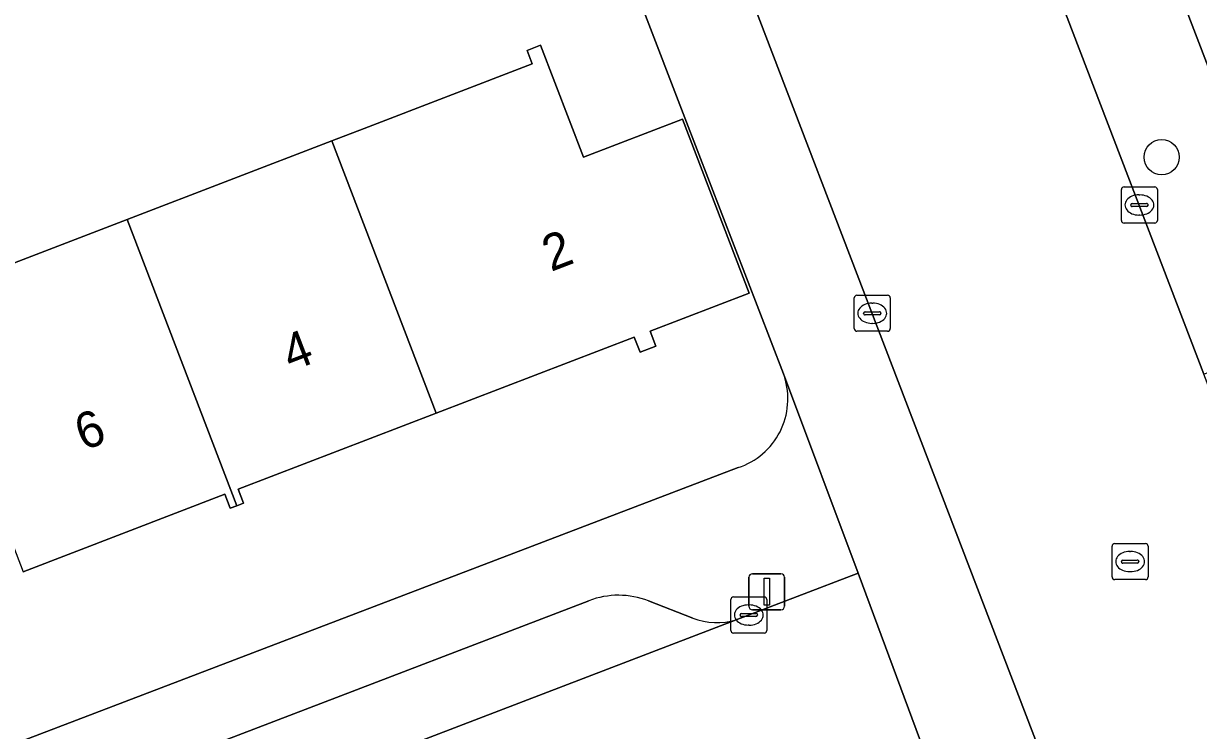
# Model space of a CAD drawing. Extents: x 159262 to 160143, y 383399 to 384319.
# Drawn here: x 159431.92 to 159464.54, y 383799.82 to 383819.43 of the extents above; entities that cross this region are included whole.
import ezdxf

# ---------------------------------------------------------------- set-up
doc = ezdxf.new("R2010")
doc.units = 0
for name, color, linetype in [('IMGEO_Boom', 7, 'Continuous'), ('IMGEO_Erf', 7, 'Continuous'), ('IMGEO_Kolk', 7, 'Continuous'), ('IMGEO_Lichtmast', 7, 'Continuous'), ('IMGEO_Muur', 7, 'Continuous'), ('IMGEO_Pand', 7, 'Continuous'), ('IMGEO_Pand_nummerreeks', 7, 'Continuous'), ('IMGEO_Parkeervlak_open', 7, 'Continuous'), ('IMGEO_Rijbaan_lokaal_gesloten', 7, 'Continuous'), ('IMGEO_Rijbaan_lokaal_open', 7, 'Continuous'), ('IMGEO_Rioolput', 7, 'Continuous'), ('IMGEO_Voetpad_open', 7, 'Continuous')]:
    doc.layers.add(name, color=color, linetype=linetype)

msp = doc.modelspace()

# ---------------------------------------------------------------- linework, layer by layer
at = {"layer": 'IMGEO_Boom'}
msp.add_circle((159463.514, 383815.72), 0.489, dxfattribs=at)
at = {"layer": 'IMGEO_Erf'}
for points in [[(159458.43, 383834.836), (159491.014, 383750), (159493.662, 383742.956), (159500, 383726.102), (159501.344, 383722.528)], [(159450.279, 383816.807), (159446.811, 383825.818), (159443.971, 383824.732), (159437.947, 383822.429), (159437.414, 383823.824), (159433.631, 383822.378), (159432.738, 383824.713), (159417.335, 383818.711), (159417.833, 383817.432), (159414.014, 383815.943), (159410.168, 383814.444), (159409.503, 383816.15), (159382.374, 383805.575), (159383.454, 383802.753), (159384.533, 383799.932), (159385.613, 383797.11), (159386.692, 383794.288), (159387.772, 383791.467), (159388.851, 383788.645), (159382.929, 383786.384), (159382.814, 383786.685), (159376.601, 383784.307)], [(159429.014, 383811.769), (159434.794, 383813.989), (159440.475, 383816.171), (159441.372, 383816.516), (159446.039, 383818.309), (159445.895, 383818.681), (159446.268, 383818.825), (159447.459, 383815.72), (159450.214, 383816.776), (159452.065, 383811.948), (159449.311, 383810.891), (159449.469, 383810.478), (159449.032, 383810.311), (159448.874, 383810.724), (159443.375, 383808.615), (159437.877, 383806.507), (159438.025, 383806.121), (159437.84, 383806.05), (159437.657, 383805.98), (159437.508, 383806.368), (159431.909, 383804.221)], [(159453.039, 383809.632), (159453.011, 383809.711), (159450.279, 383816.807)], [(159379.948, 383779.592), (159397.972, 383786.591), (159451.753, 383807.11)]]:
    msp.add_lwpolyline(points, dxfattribs=at)
msp.add_arc((159451.138, 383809.012), 1.999, 287.9124, 18.0524, dxfattribs=at)
at = {"layer": 'IMGEO_Kolk'}
for p, q in [((159462.395, 383813.967), (159462.395, 383814.819)), ((159462.47, 383814.893), (159463.322, 383814.893)), ((159463.396, 383814.819), (159463.396, 383813.967)), ((159462.883, 383814.673), (159462.908, 383814.673)), ((159462.654, 383814.387), (159462.654, 383814.399)), ((159463.092, 383814.35), (159462.694, 383814.35)), ((159462.697, 383814.436), (159463.095, 383814.436)), ((159463.138, 383814.399), (159463.138, 383814.387)), ((159463.322, 383813.893), (159462.47, 383813.893)), ((159462.906, 383814.113), (159462.881, 383814.113)), ((159455.054, 383811.889), (159455.906, 383811.889)), ((159454.979, 383810.963), (159454.979, 383811.815)), ((159455.467, 383811.669), (159455.492, 383811.669)), ((159455.98, 383811.815), (159455.98, 383810.963)), ((159455.238, 383811.383), (159455.238, 383811.395)), ((159455.676, 383811.346), (159455.278, 383811.346)), ((159455.281, 383811.432), (159455.679, 383811.432)), ((159455.722, 383811.395), (159455.722, 383811.383)), ((159455.906, 383810.889), (159455.054, 383810.889)), ((159455.49, 383811.109), (159455.465, 383811.109)), ((159451.551, 383802.593), (159451.551, 383803.445)), ((159451.626, 383803.519), (159452.478, 383803.519)), ((159452.552, 383803.445), (159452.552, 383802.593)), ((159451.853, 383803.062), (159452.251, 383803.062)), ((159452.039, 383803.299), (159452.064, 383803.299)), ((159451.81, 383803.013), (159451.81, 383803.025)), ((159452.248, 383802.976), (159451.85, 383802.976)), ((159452.062, 383802.739), (159452.037, 383802.739)), ((159452.294, 383803.025), (159452.294, 383803.013)), ((159452.478, 383802.519), (159451.626, 383802.519))]:
    msp.add_line(p, q, dxfattribs=at)
for points in [[(159462.395, 383813.967), (159462.395, 383814.819)], [(159462.47, 383814.893), (159463.322, 383814.893)], [(159463.396, 383814.819), (159463.396, 383813.967)], [(159463.322, 383813.893), (159462.47, 383813.893)], [(159455.054, 383811.889), (159455.906, 383811.889)], [(159454.979, 383810.963), (159454.979, 383811.815)], [(159455.98, 383811.815), (159455.98, 383810.963)], [(159455.906, 383810.889), (159455.054, 383810.889)], [(159451.551, 383802.593), (159451.551, 383803.445)], [(159451.626, 383803.519), (159452.478, 383803.519)], [(159452.552, 383803.445), (159452.552, 383802.593)], [(159452.478, 383802.519), (159451.626, 383802.519)]]:
    msp.add_lwpolyline(points, dxfattribs=at)
for centre, radius, start, end in [((159462.472, 383814.817), 0.0765, 91.552, 178.448), ((159462.472, 383814.817), 0.0765, 91.552, 178.448), ((159463.32, 383814.817), 0.0765, 1.552, 88.448), ((159463.32, 383814.817), 0.0765, 1.552, 88.448), ((159462.694, 383814.396), 0.0403, 85.8775, 175.7526), ((159462.691, 383814.386), 0.0366, 178.938, 274.7102), ((159463.095, 383814.393), 0.043, 264.8664, 352.4533), ((159463.099, 383814.398), 0.0386, 1.7309, 96.639), ((159462.472, 383813.969), 0.0765, 181.552, 268.448), ((159462.472, 383813.969), 0.0765, 181.552, 268.448), ((159463.32, 383813.969), 0.0765, 271.552, 358.448), ((159463.32, 383813.969), 0.0765, 271.552, 358.448), ((159455.056, 383811.813), 0.0765, 91.552, 178.448), ((159455.056, 383811.813), 0.0765, 91.552, 178.448), ((159455.904, 383811.813), 0.0765, 1.552, 88.448), ((159455.904, 383811.813), 0.0765, 1.552, 88.448), ((159455.278, 383811.392), 0.0403, 85.8775, 175.7526), ((159455.275, 383811.382), 0.0366, 178.938, 274.7102), ((159455.679, 383811.389), 0.043, 264.8664, 352.4533), ((159455.683, 383811.394), 0.0386, 1.7309, 96.639), ((159455.056, 383810.965), 0.0765, 181.552, 268.448), ((159455.056, 383810.965), 0.0765, 181.552, 268.448), ((159455.904, 383810.965), 0.0765, 271.552, 358.448), ((159455.904, 383810.965), 0.0765, 271.552, 358.448), ((159451.628, 383803.443), 0.0765, 91.552, 178.448), ((159451.628, 383803.443), 0.0765, 91.552, 178.448), ((159452.476, 383803.443), 0.0765, 1.552, 88.448), ((159452.476, 383803.443), 0.0765, 1.552, 88.448), ((159451.85, 383803.022), 0.0403, 85.8775, 175.7526), ((159452.255, 383803.024), 0.0386, 1.7309, 96.639), ((159451.847, 383803.012), 0.0366, 178.938, 274.7102), ((159452.251, 383803.019), 0.043, 264.8664, 352.4533), ((159451.628, 383802.595), 0.0765, 181.552, 268.448), ((159451.628, 383802.595), 0.0765, 181.552, 268.448), ((159452.476, 383802.595), 0.0765, 271.552, 358.448), ((159452.476, 383802.595), 0.0765, 271.552, 358.448)]:
    msp.add_arc(centre, radius, start, end, dxfattribs=at)
for centre, major_axis, ratio, start_param, end_param in [((159462.882, 383814.393), (-0.387, 0.002), 0.722429, 4.712389, 7.853982), ((159462.907, 383814.393), (-0.39, 0.002), 0.717154, 1.570796, 4.712389), ((159455.466, 383811.389), (-0.387, 0.002), 0.722429, 4.712389, 7.853982), ((159455.491, 383811.389), (-0.39, 0.002), 0.717154, 1.570796, 4.712389), ((159452.038, 383803.019), (-0.387, 0.002), 0.722429, 4.712389, 7.853982), ((159452.063, 383803.019), (-0.39, 0.002), 0.717154, 1.570796, 4.712389)]:
    msp.add_ellipse(centre, major_axis=major_axis, ratio=ratio, start_param=start_param, end_param=end_param, dxfattribs=at)
at = {"layer": 'IMGEO_Lichtmast'}
for p, q in [((159452.055, 383803.264), (159452.055, 383804.064)), ((159452.055, 383804.064), (159452.055, 383803.264)), ((159452.155, 383804.164), (159452.945, 383804.164)), ((159452.945, 383804.164), (159452.155, 383804.164)), ((159453.045, 383804.064), (159453.045, 383803.264)), ((159453.045, 383803.264), (159453.045, 383804.064)), ((159452.945, 383803.164), (159452.155, 383803.164)), ((159452.155, 383803.164), (159452.945, 383803.164))]:
    msp.add_line(p, q, dxfattribs=at)
msp.add_lwpolyline([(159452.475, 383804.039), (159452.625, 383804.039), (159452.625, 383803.289), (159452.475, 383803.289), (159452.475, 383804.039)], dxfattribs=at)
for centre, start, end in [((159452.155, 383804.064), 90, 180), ((159452.155, 383804.064), 90, 180), ((159452.945, 383804.064), 0, 90), ((159452.945, 383804.064), 360, 90), ((159452.155, 383803.264), 180, 270), ((159452.155, 383803.264), 180, 270), ((159452.945, 383803.264), 270, 0), ((159452.945, 383803.264), 270, 0)]:
    msp.add_arc(centre, 0.1, start, end, dxfattribs=at)
at = {"layer": 'IMGEO_Muur'}
msp.add_lwpolyline([(159446.811, 383825.818), (159450.279, 383816.807)], dxfattribs=at)
at = {"layer": 'IMGEO_Pand'}
for points in [[(159440.475, 383816.171), (159443.375, 383808.615), (159448.874, 383810.724), (159449.032, 383810.311), (159449.469, 383810.478), (159449.311, 383810.891), (159452.065, 383811.948), (159450.214, 383816.776), (159447.459, 383815.72), (159446.268, 383818.825), (159445.895, 383818.681), (159446.039, 383818.309), (159441.372, 383816.516)], [(159437.84, 383806.05), (159438.025, 383806.121), (159437.877, 383806.507), (159443.375, 383808.615), (159440.475, 383816.171), (159434.794, 383813.989)], [(159437.84, 383806.05), (159434.794, 383813.989), (159429.014, 383811.769), (159431.909, 383804.221), (159437.508, 383806.368), (159437.657, 383805.98)]]:
    msp.add_lwpolyline(points, close=True, dxfattribs=at)
at = {"layer": 'IMGEO_Parkeervlak_open'}
for points in [[(159447.613, 383803.415), (159430.113, 383796.714), (159413.143, 383790.204), (159398.196, 383784.571), (159393.78, 383782.895), (159390.277, 383781.527), (159385.087, 383779.494)], [(159450.495, 383802.935), (159449.268, 383803.411)], [(159382.731, 383776.545), (159398.361, 383782.558), (159413.843, 383788.378), (159430.813, 383794.888), (159451.704, 383802.889)]]:
    msp.add_lwpolyline(points, dxfattribs=at)
for centre, radius, start, end in [((159448.435, 383801.267), 2.3, 68.7769, 110.9462), ((159451.165, 383804.635), 1.827, 248.4846, 287.1575)]:
    msp.add_arc(centre, radius, start, end, dxfattribs=at)
at = {"layer": 'IMGEO_Rijbaan_lokaal_gesloten'}
msp.add_lwpolyline([(159483.308, 383761.046), (159483.224, 383761.306), (159479.585, 383770.783), (159477.396, 383776.499), (159473.023, 383787.916), (159471.145, 383792.82), (159467.126, 383803.315), (159464.68, 383809.703), (159460.676, 383820.157), (159458.217, 383826.578), (159457.134, 383829.395), (159449.663, 383826.529), (159449.79, 383826.168), (159450.958, 383823.16), (159466.558, 383782.495), (159469.529, 383774.749), (159472.225, 383767.721), (159475.5, 383759.023), (159475.831, 383758.13)], close=True, dxfattribs=at)
at = {"layer": 'IMGEO_Rijbaan_lokaal_open'}
msp.add_lwpolyline([(159420.987, 383785.667), (159432.691, 383790.083), (159442.971, 383794.05), (159451.565, 383797.259), (159454.155, 383798.309), (159456.91, 383799.271), (159455.084, 383804.175), (159451.704, 383802.889), (159430.813, 383794.888), (159413.843, 383788.378), (159398.361, 383782.558), (159382.731, 383776.545), (159384.569, 383771.758), (159399.847, 383777.623), (159409.934, 383781.376)], close=True, dxfattribs=at)
at = {"layer": 'IMGEO_Rioolput'}
for p, q in [((159462.212, 383805.001), (159463.064, 383805.001)), ((159462.137, 383804.075), (159462.137, 383804.927)), ((159462.625, 383804.781), (159462.65, 383804.781)), ((159463.138, 383804.927), (159463.138, 383804.075)), ((159462.396, 383804.495), (159462.396, 383804.507)), ((159462.834, 383804.458), (159462.436, 383804.458)), ((159462.439, 383804.544), (159462.837, 383804.544)), ((159462.88, 383804.507), (159462.88, 383804.495)), ((159462.648, 383804.221), (159462.623, 383804.221)), ((159463.064, 383804.001), (159462.212, 383804.001))]:
    msp.add_line(p, q, dxfattribs=at)
for points in [[(159462.212, 383805.001), (159463.064, 383805.001)], [(159462.137, 383804.075), (159462.137, 383804.927)], [(159463.138, 383804.927), (159463.138, 383804.075)], [(159463.064, 383804.001), (159462.212, 383804.001)]]:
    msp.add_lwpolyline(points, dxfattribs=at)
for centre, radius, start, end in [((159462.214, 383804.925), 0.0765, 91.552, 178.448), ((159462.214, 383804.925), 0.0765, 91.552, 178.448), ((159463.062, 383804.925), 0.0765, 1.552, 88.448), ((159463.062, 383804.925), 0.0765, 1.552, 88.448), ((159462.436, 383804.504), 0.0403, 85.8775, 175.7526), ((159462.433, 383804.494), 0.0366, 178.938, 274.7102), ((159462.837, 383804.501), 0.043, 264.8664, 352.4533), ((159462.841, 383804.506), 0.0386, 1.7309, 96.639), ((159462.214, 383804.077), 0.0765, 181.552, 268.448), ((159462.214, 383804.077), 0.0765, 181.552, 268.448), ((159463.062, 383804.077), 0.0765, 271.552, 358.448), ((159463.062, 383804.077), 0.0765, 271.552, 358.448)]:
    msp.add_arc(centre, radius, start, end, dxfattribs=at)
for centre, major_axis, ratio, start_param, end_param in [((159462.624, 383804.501), (-0.387, 0.002), 0.722429, 4.712389, 7.853982), ((159462.649, 383804.501), (-0.39, 0.002), 0.717154, 1.570796, 4.712389)]:
    msp.add_ellipse(centre, major_axis=major_axis, ratio=ratio, start_param=start_param, end_param=end_param, dxfattribs=at)
at = {"layer": 'IMGEO_Voetpad_open'}
for points in [[(159436.942, 383851.268), (159438.361, 383847.773), (159444.835, 383830.954), (159445.377, 383829.545), (159446.811, 383825.818), (159450.279, 383816.807), (159453.011, 383809.711), (159453.039, 383809.632), (159455.084, 383804.175), (159456.91, 383799.271), (159457.253, 383798.289), (159458.547, 383794.996)], [(159491.014, 383750), (159458.43, 383834.836)], [(159476.042, 383757.553), (159475.831, 383758.13), (159475.5, 383759.023), (159472.225, 383767.721), (159469.529, 383774.749), (159469.063, 383774.57), (159466.092, 383782.316), (159466.558, 383782.495), (159450.958, 383823.16)], [(159460.676, 383820.157), (159464.68, 383809.703), (159465.146, 383809.881), (159467.592, 383803.493), (159467.126, 383803.315), (159471.145, 383792.82), (159471.611, 383792.998), (159473.489, 383788.094), (159473.023, 383787.916), (159477.396, 383776.499), (159477.862, 383776.677), (159480.051, 383770.961), (159479.585, 383770.783), (159483.224, 383761.306)], [(159451.704, 383802.889), (159455.084, 383804.175), (159453.039, 383809.632)], [(159451.753, 383807.11), (159397.972, 383786.591), (159379.948, 383779.592)], [(159385.087, 383779.494), (159390.277, 383781.527), (159390.1, 383781.947), (159393.632, 383783.306), (159393.78, 383782.895), (159398.196, 383784.571), (159413.143, 383790.204), (159430.113, 383796.714), (159447.613, 383803.415)], [(159449.268, 383803.411), (159450.495, 383802.935)]]:
    msp.add_lwpolyline(points, dxfattribs=at)
for centre, radius, start, end in [((159451.138, 383809.012), 1.999, 287.9124, 18.0524), ((159448.435, 383801.267), 2.3, 68.7769, 110.9462), ((159451.165, 383804.635), 1.827, 248.4846, 287.1575)]:
    msp.add_arc(centre, radius, start, end, dxfattribs=at)

# ---------------------------------------------------------------- texts
at = {"layer": 'IMGEO_Pand_nummerreeks'}
for s, rotation, p in [('2', 20.9802, (159446.559, 383812.534)), ('4', 20.935, (159439.339, 383809.769)), ('6', 20.935, (159433.583, 383807.567))]:
    msp.add_text(s, height=1, rotation=rotation, dxfattribs=at).set_placement(p)

doc.saveas('drawing.dxf')
